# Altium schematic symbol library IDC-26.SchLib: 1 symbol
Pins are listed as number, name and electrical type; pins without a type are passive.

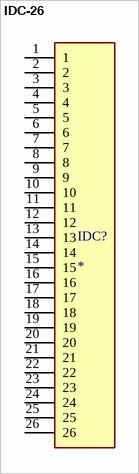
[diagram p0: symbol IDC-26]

## IDC-26
designator IDC?
IDC LOW PRO HDR 26P VERT BLUE; Centerline_Pitch: 2.54 mm[.1 in]; Product_Type: Connector; MF: TE Connectivity; Number_of_Positions: 26; MP: 2-1761679-9
footprint IDC-26
pins: 1, 2, 3, 4, 5, 6, 7, 8, 9, 10, 11, 12, 13, 14, 15, 16, 17, 18, 19, 20, 21, 22, 23, 24, 25, 26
